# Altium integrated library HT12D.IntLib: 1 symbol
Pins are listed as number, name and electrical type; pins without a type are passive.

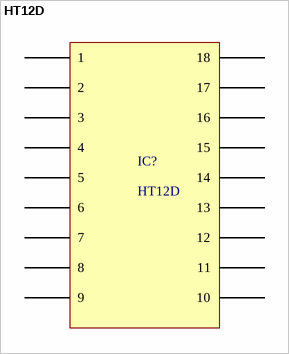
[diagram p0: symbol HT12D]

## HT12D
designator IC?
footprint HT12D
pins: 1, 2, 3, 4, 5, 6, 7, 8, 9, 10, 11, 12, 13, 14, 15, 16, 17, 18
